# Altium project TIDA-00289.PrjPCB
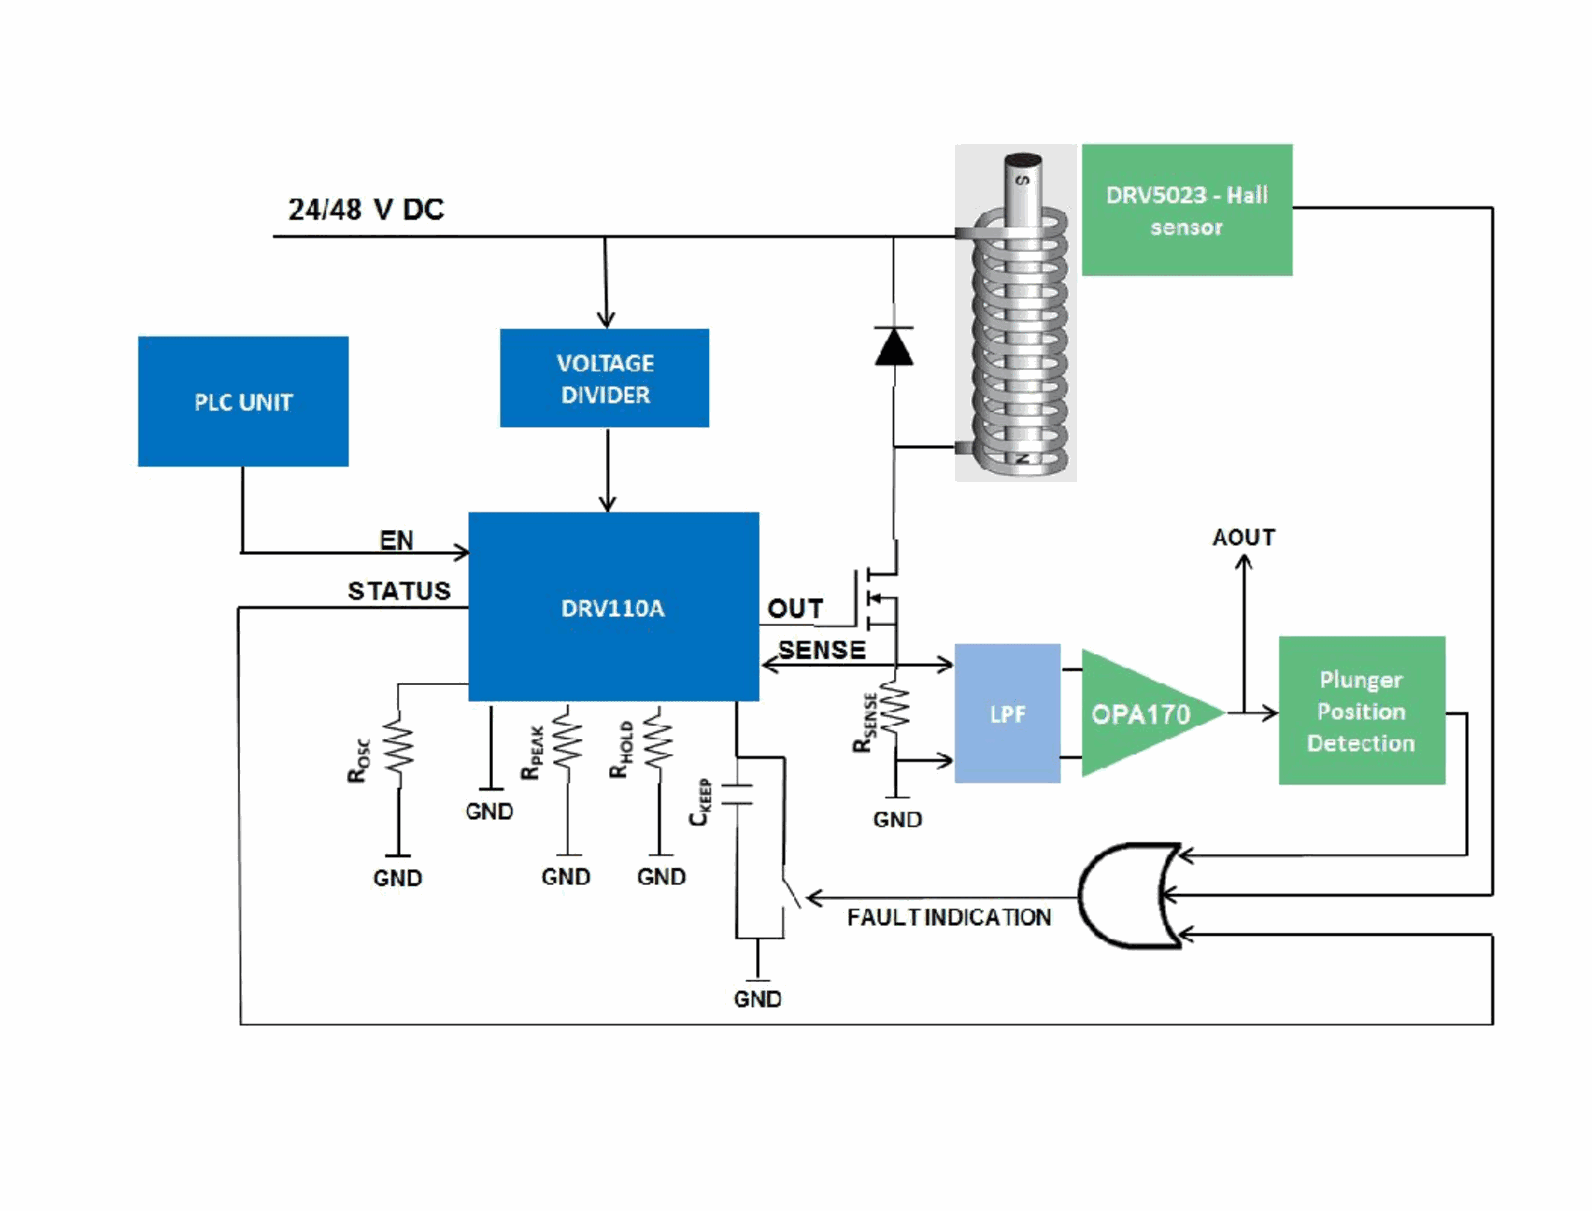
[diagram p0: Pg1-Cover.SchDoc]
CopyrightYear: 2014; PCB_Layout: Sharanu; PCB_Rev: E2; PRJ_Customer: Public Release; PRJ_Engineer: Manu B; PRJ_Number: TIDA-00289; PRJ_Title: Current Controlled Solenoid Driver; SCH_Rev: E2; TechSupport: http://www.ti.com/support
3 sheets, 83 parts. Net scope: global (net labels, ports and power ports of the same name join across sheets).
Board file: TIDA-00289.PcbDoc
Sheets:
  Pg1-Cover.SchDoc
  Pg2-Main.SchDoc
  Pg3_Hardware_ANSI-B.SchDoc

## Sheet Pg1-Cover.SchDoc: Block Diagram
size 431 x 279 mm; Date: Not shown in title block; ApprovedBy: Not shown in title block; CheckedBy: Not shown in title block; Author: Not shown in title block; CompanyName: Not shown in title block; Engineer: Not shown in title block; Organization: Not shown in title block; Address1: Not shown in title block; Address2: Not shown in title block; Address3: Not shown in title block; Address4: Not shown in title block; DocumentNumber: 1; Revision: Use project parameter SCH_Rev; SheetNumber: 1; SheetTotal: 3; PageSetup: Record=PageOptions|CenterHorizontal=True|CenterVertical=True|PrintScale=1.00|XCorrection=1.00|YCorrection=1.00|PrintKind=0|BorderSize=5000000|LeftOffset=0|BottomOffset=0|Orientation=2|PaperLength=1000|PaperWidth=1000|Scale=100|PaperSource=15|PrintQuality=600|MediaType=1|DitherType=10|PaperKind=Letter|PrintScaleMode=1

## Sheet Pg2-Main.SchDoc: Main
size 431 x 279 mm; Date: Not shown in title block; ApprovedBy: Not shown in title block; CheckedBy: Not shown in title block; Author: Not shown in title block; CompanyName: Not shown in title block; DrawnBy: Sanjay Pithadia; Engineer: Not shown in title block; Organization: Not shown in title block; Address1: Not shown in title block; Address2: Not shown in title block; Address3: Not shown in title block; Address4: Not shown in title block; DocumentNumber: 2; Revision: Use project parameter SCH_Rev; SheetNumber: 2; SheetTotal: 3; PageSetup: Record=PageOptions|CenterHorizontal=True|CenterVertical=True|PrintScale=1.00|XCorrection=1.00|YCorrection=1.00|PrintKind=0|BorderSize=5000000|LeftOffset=0|BottomOffset=0|Orientation=2|PaperLength=1000|PaperWidth=1000|Scale=100|PaperSource=15|PrintQuality=600|MediaType=1|DitherType=10|PaperKind=Letter|PrintScaleMode=1
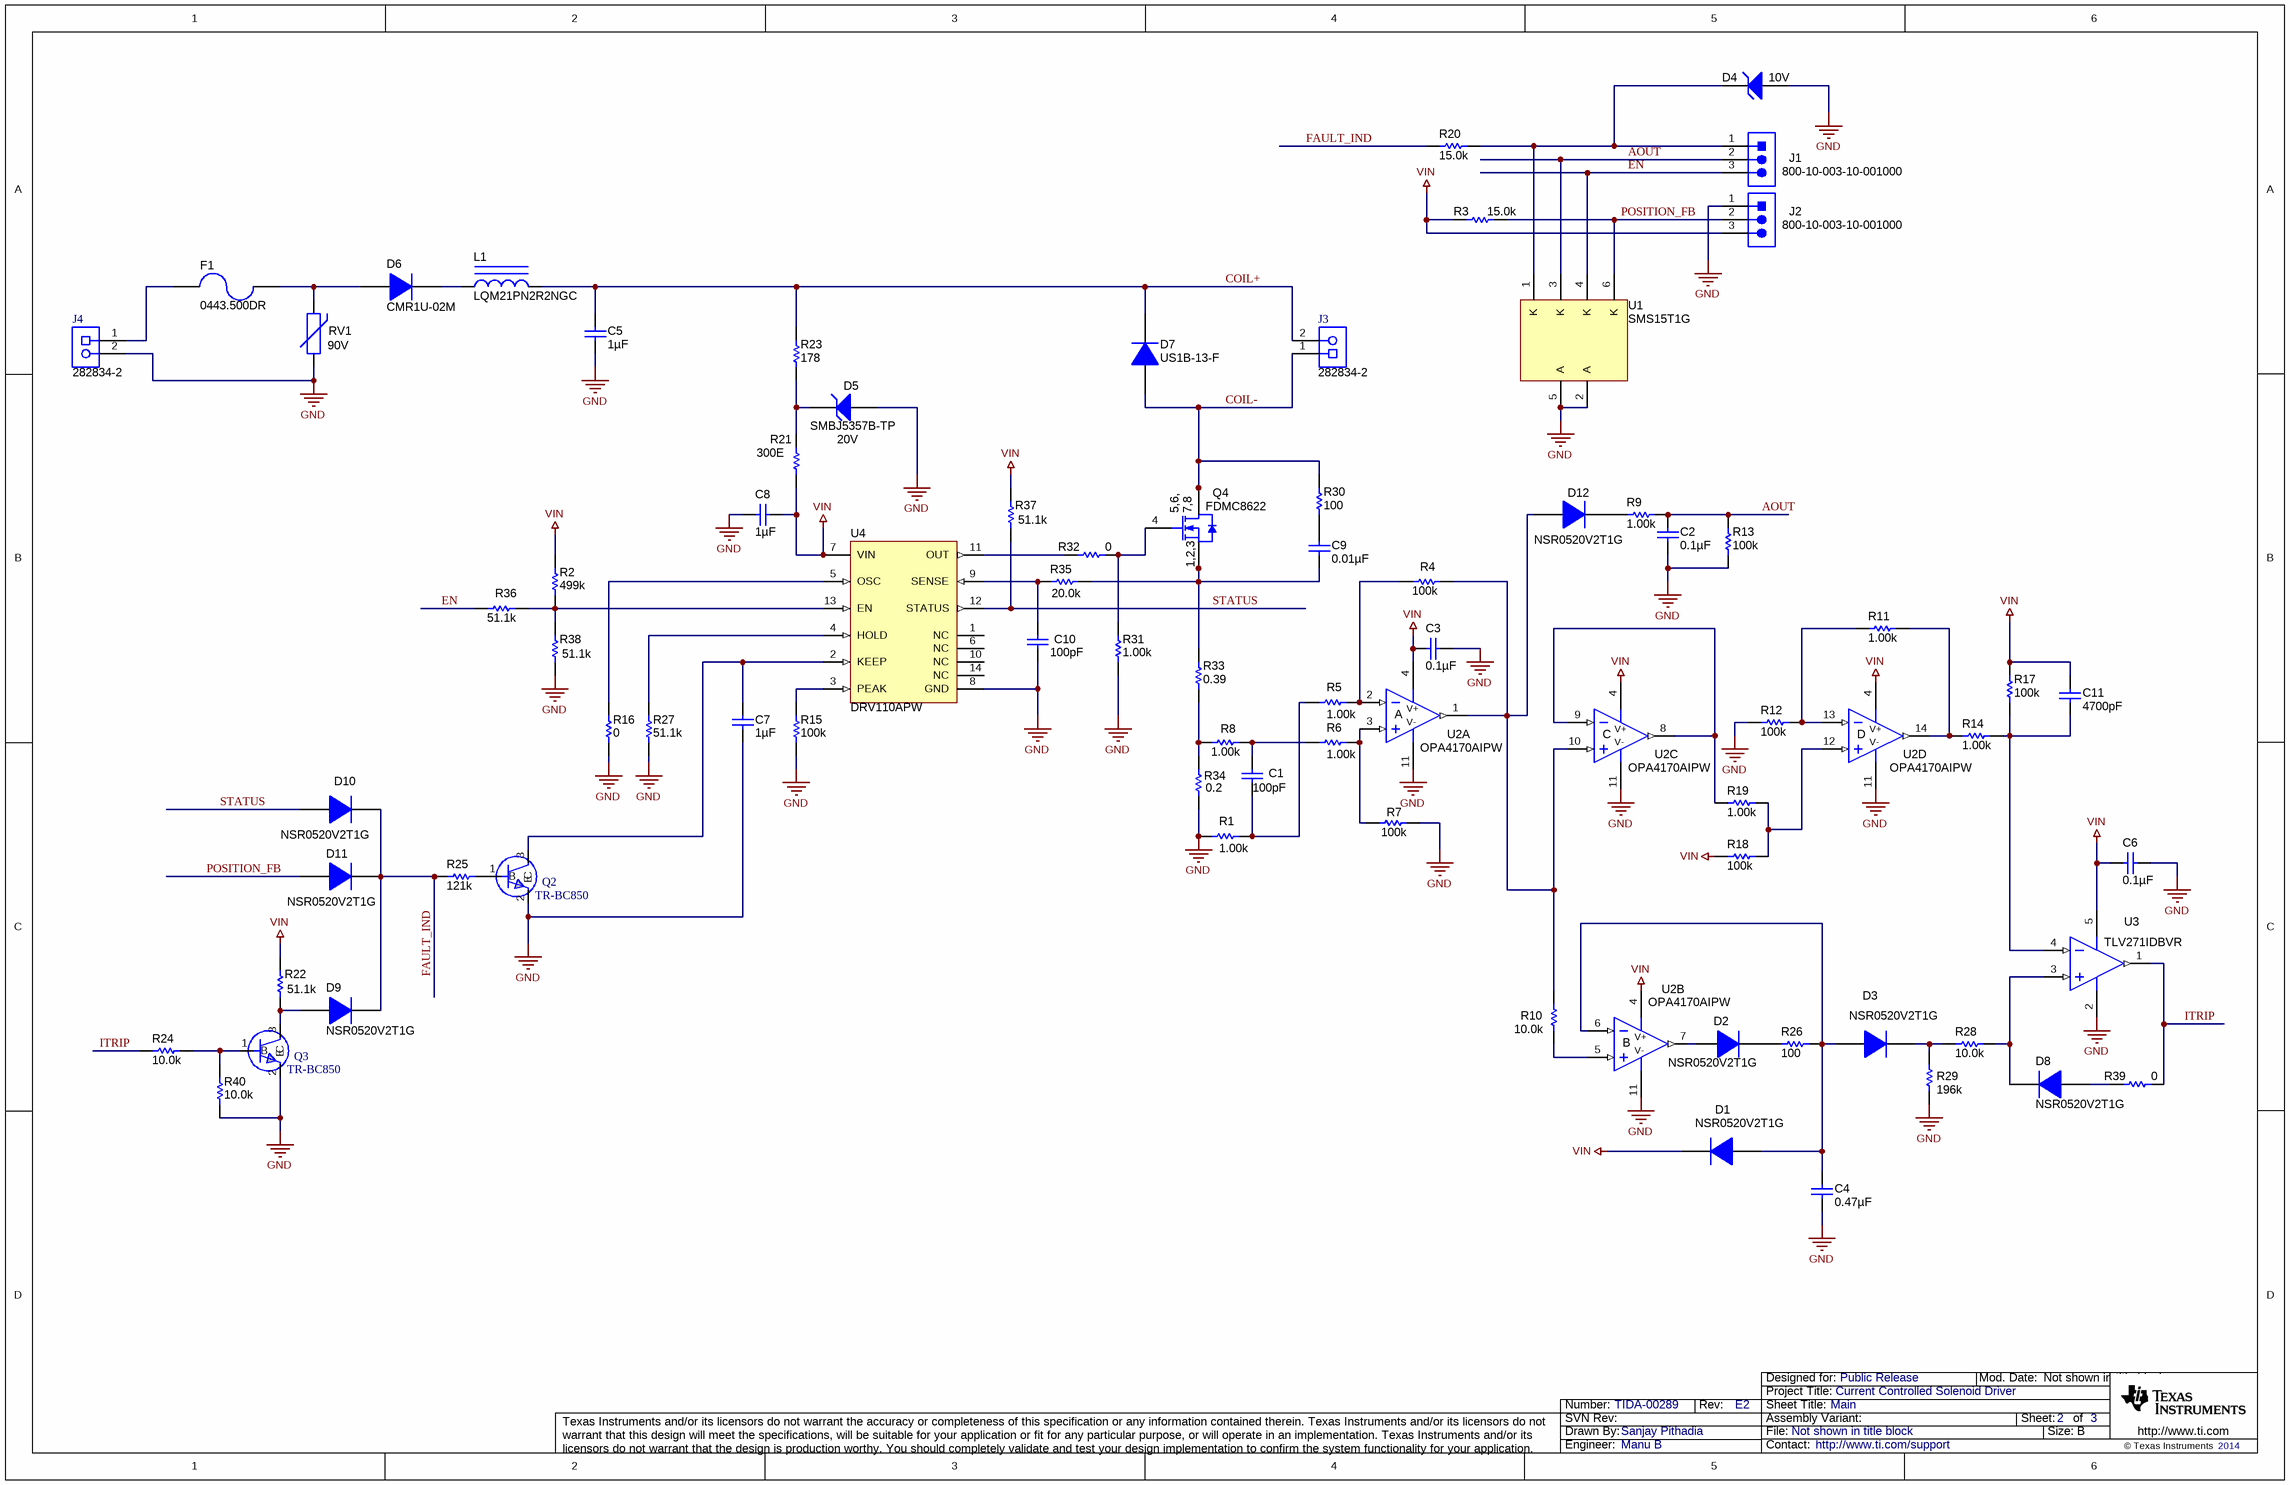
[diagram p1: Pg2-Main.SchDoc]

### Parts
C1  ValueDisplayed: 100pF  [0603]  (hidden comment: 06035A101JAT2A)
C2  ValueDisplayed: 0.1µF  [0603]  (hidden comment: GRM188R71E104KA01D)
C3  ValueDisplayed: 0.1µF  [0603]  (hidden comment: GRM188R71E104KA01D)
C4  ValueDisplayed: 0.47µF  [0603]  (hidden comment: GRM188R71E474KA12D)
C5  ValueDisplayed: 1µF  [1210]  (hidden comment: C3225X7R2A105K200AA)
C6  ValueDisplayed: 0.1µF  [0603]  (hidden comment: GRM188R71E104KA01D)
C7  ValueDisplayed: 1µF  [0603]  (hidden comment: C0603C105K8PACTU)
C8  ValueDisplayed: 1µF  [0603]  (hidden comment: GMK107BJ105KA-T)
C9  ValueDisplayed: 0.01µF  [0805_HV]  (hidden comment: 08051C103KAT2A)
C10  ValueDisplayed: 100pF  [0603]  (hidden comment: 06035A101JAT2A)
C11  ValueDisplayed: 4700pF  [0603]  (hidden comment: GRM188R71E472KA01D)
D1  NSR0520V2T1G  [SOD-523]
D2  NSR0520V2T1G  [SOD-523]
D3  NSR0520V2T1G  [SOD-523]
D4  value 10V  [SOD-123]  (hidden comment: MMSZ5240B-7-F)
D5  SMBJ5357B-TP  value 20V  [SMB]
D6  CMR1U-02M  [SMA]
D7  US1B-13-F  [SMA]
D8  NSR0520V2T1G  [SOD-523]
D9  NSR0520V2T1G  [SOD-523]
D10  NSR0520V2T1G  [SOD-523]
D11  NSR0520V2T1G  [SOD-523]
D12  NSR0520V2T1G  [SOD-523]
F1  0443.500DR  [FUSE_0443]
J1  800-10-003-10-001000  [Connector_GRPB031VWVN-RC]
J2  800-10-003-10-001000  [Connector_GRPB031VWVN-RC]
J3  282834-2  [TEC_282834-2]
J4  282834-2  [TEC_282834-2]
L1  LQM21PN2R2NGC  [0805_HV]
Q2  TR-BC850  [SOT-23]
Q3  TR-BC850  [SOT-23]
Q4  FDMC8622  [PG-TSDSON-8]
R1  value 1.00k  [0603]  (hidden comment: RC0603FR-071KL)
R2  ValueDisplayed: 499k  [0603]  (hidden comment: CRCW0603499KFKEA)
R3  ValueDisplayed: 15.0k  [0603]  (hidden comment: CRCW060315K0FKEA)
R4  ValueDisplayed: 100k  [0603]  (hidden comment: CRCW0603100KFKEA)
R5  value 1.00k  [0603]  (hidden comment: RC0603FR-071KL)
R6  value 1.00k  [0603]  (hidden comment: RC0603FR-071KL)
R7  ValueDisplayed: 100k  [0603]  (hidden comment: CRCW0603100KFKEA)
R8  value 1.00k  [0603]  (hidden comment: RC0603FR-071KL)
R9  value 1.00k  [0603]  (hidden comment: RC0603FR-071KL)
R10  value 10.0k  [0603]  (hidden comment: RT0603BRD0710KL)
R11  value 1.00k  [0603]  (hidden comment: RC0603FR-071KL)
R12  ValueDisplayed: 100k  [0603]  (hidden comment: CRCW0603100KFKEA)
R13  ValueDisplayed: 100k  [0603]  (hidden comment: CRCW0603100KFKEA)
R14  value 1.00k  [0603]  (hidden comment: RC0603FR-071KL)
R15  ValueDisplayed: 100k  [0603]  (hidden comment: CRCW0603100KFKEA)
R16  value 0  [0603]  (hidden comment: CRCW06030000Z0EA)
R17  ValueDisplayed: 100k  [0603]  (hidden comment: CRCW0603100KFKEA)
R18  ValueDisplayed: 100k  [0603]  (hidden comment: CRCW0603100KFKEA)
R19  value 1.00k  [0603]  (hidden comment: RC0603FR-071KL)
R20  ValueDisplayed: 15.0k  [0603]  (hidden comment: CRCW060315K0FKEA)
R21  value 300E  [1210M]  (hidden comment: ERJ-14YJ301U)
R22  ValueDisplayed: 51.1k  [0603]  (hidden comment: CRCW060351K1FKEA)
R23  value 178  [2010]  (hidden comment: CRCW2010178RFKEF)
R24  value 10.0k  [0603]  (hidden comment: RT0603BRD0710KL)
R25  ValueDisplayed: 121k  [0603]  (hidden comment: CRCW0603121KFKEA)
R26  ValueDisplayed: 100  [0603]  (hidden comment: CRCW0603100RFKEA)
R27  ValueDisplayed: 51.1k  [0603]  (hidden comment: CRCW060351K1FKEA)
R28  value 10.0k  [0603]  (hidden comment: RT0603BRD0710KL)
R29  ValueDisplayed: 196k  [0603]  (hidden comment: CRCW0603196KFKEA)
R30  value 100  [0805_HV]  (hidden comment: RT0805BRD07100RL)
R31  value 1.00k  [0603]  (hidden comment: RC0603FR-071KL)
R32  value 0  [0603]  (hidden comment: CRCW06030000Z0EA)
R33  value 0.39  [1210M]  (hidden comment: MCR25JZHFLR390)
R34  value 0.2  [1210M]  (hidden comment: MCR25JZHFLR200)
R35  ValueDisplayed: 20.0k  [0603]  (hidden comment: CRCW060320K0FKEA)
R36  ValueDisplayed: 51.1k  [0603]  (hidden comment: CRCW060351K1FKEA)
R37  ValueDisplayed: 51.1k  [0603]  (hidden comment: CRCW060351K1FKEA)
R38  ValueDisplayed: 51.1k  [0603]  (hidden comment: CRCW060351K1FKEA)
R39  value 0  [0603]  (hidden comment: CRCW06030000Z0EA)
R40  value 10.0k  [0603]  (hidden comment: RT0603BRD0710KL)
RV1  value 90V  [VAR_V100ZA4P]  (hidden comment: V100ZA4P)
U1  SMS15T1G  [DBV0006A_N]
U2  OPA4170AIPW  [PW0014A_N]  (parts A,B,C,D of 4)
U3  TLV271IDBVR  [DBV0005A_N]
U4  DRV110APW  [PW0014A_N]

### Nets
GND: C2.2 C3.1 C4.2 C5.2 C6.1 C7.1 C8.2 C10.2 D4.2(A) D5.2(A) J2.1 J4.2 Q2.2(E) Q3.2(E) R1.2 R7.1 R12.1 R13.1 R15.2 R16.2 R27.1 R29.1 R31.1 R34.1 R38.1 R40.1 RV1.1 U1.2(A) U1.5(A) U2.11(V-) U3.2(GND) U4.8(GND)
VIN: C3.2 C6.2 C8.1 C11.2 D1.1(K) J2.3 R2.1 R3.1 R17.1 R18.1 R21.1 R22.2 R37.2 U2.4(V+) U3.5(VDD) U4.7(VIN)
AOUT: C2.1 J1.2 R9.2 R13.2 U1.3(K)
COIL+: C5.1 D7.1(K) J3.2 L1.2 R23.2
COIL-: D7.2(A) J3.1 Q4.5(D) Q4.6(D) Q4.7(D) Q4.8(D) Q4.9(D) R30.2
EN: J1.3 R36.2 U1.4(K)
FAULT_IND: D9.1(K) D10.1(K) D11.1(K) R20.1 R25.1
ITRIP: R24.2 R39.2 U3.1(OUT)
POSITION_FB: D11.2(A) J2.2 R3.2 U1.6(K)
STATUS: D10.2(A) R37.1 U4.12(STATUS)
NetC1_1: C1.1 R6.2 R8.2
NetC1_2: C1.2 R1.1 R5.2
NetC4_1: C4.1 D1.2(A) D3.2(A) R26.2 U2.6(IN-)
NetC7_2: C7.2 Q2.3(C) U4.2(KEEP)
NetC9_1: C9.1 R30.1
NetC9_2: C9.2 Q4.1(S) Q4.2(S) Q4.3(S) R33.2 R35.2
NetC10_1: C10.1 R35.1 U4.9(SENSE)
NetC11_1: C11.1 R14.2 R17.2 U3.4(IN-)
NetD2_1: D2.1(K) R26.1
NetD2_2: D2.2(A) U2.7(OUT)
NetD3_1: D3.1(K) R28.1 R29.2
NetD4_1: D4.1(K) J1.1 R20.2 U1.1(K)
NetD5_1: D5.1(K) R21.2 R23.1
NetD6_1: D6.1(K) L1.1
NetD6_2: D6.2(A) F1.1 RV1.2
NetD8_1: D8.1(K) R28.2 U3.3(IN+)
NetD8_2: D8.2(A) R39.1
NetD9_2: D9.2(A) Q3.3(C) R22.1
NetD12_1: D12.1(K) R9.1
NetD12_2: D12.2(A) R4.1 R10.2 U2.1(OUT) U2.10(IN+)
NetF1_2: F1.2 J4.1
NetQ2_1: Q2.1(B) R25.2
NetQ3_1: Q3.1(B) R24.1 R40.2
NetQ4_4: Q4.4(G) R31.2 R32.1
NetR2_2: R2.2 R36.1 R38.2 U4.13(EN)
NetR4_2: R4.2 R5.1 U2.2(IN-)
NetR6_1: R6.1 R7.2 U2.3(IN+)
NetR8_1: R8.1 R33.1 R34.2
NetR10_1: R10.1 U2.5(IN+)
NetR11_1: R11.1 R12.2 U2.13(IN-)
NetR11_2: R11.2 R14.1 U2.14(OUT)
NetR15_1: R15.1 U4.3(PEAK)
NetR16_1: R16.1 U4.5(OSC)
NetR18_2: R18.2 R19.2 U2.12(IN+)
NetR19_1: R19.1 U2.8(OUT) U2.9(IN-)
NetR27_2: R27.2 U4.4(HOLD)
NetR32_2: R32.2 U4.11(OUT)

Not connected (* = marked no-connect by the designer): U4 1(NC) 6(NC) 10(NC) 14(NC)

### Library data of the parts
C1 C10 = 06035A101JAT2A: CAP, CERM, 100pF, 50V, +/-5%, C0G/NP0, 0603; Manufacturer: AVX; Polarized: N; CompType: Capacitor; U/M: EA; Cap_F: 0.0000000001; Tolerance_%: 5; ESR_Ohm: 0.119; Value1: 0.119 ohm; VDC_V: 50; TaMin_C: -55; TaMax_C: 125
C2 C3 C6 = GRM188R71E104KA01D: CAP, CERM, 0.1uF, 25V, +/-10%, X7R, 0603; Manufacturer: MuRata; Polarized: N; CompType: Capacitor; U/M: EA; Cap_F: 0.0000001; Tolerance_%: 10; Value1: Unknown; VDC_V: 25; TaMin_C: -55; TaMax_C: 125
C4 = GRM188R71E474KA12D: CAP, CERM, 0.47uF, 25V, +/-10%, X7R, 0603; Manufacturer: MuRata; Polarized: N; CompType: Capacitor; U/M: EA; Cap_F: 0.00000047; Tolerance_%: 10; Value1: Unknown; VDC_V: 25; TaMin_C: -55; TaMax_C: 125
C5 = C3225X7R2A105K200AA: CAP, CERM, 1uF, 100V, +/-10%, X7R, 1210; Manufacturer: TDK; Polarized: N; CompType: Capacitor; U/M: EA; Cap_F: 0.000001; Tolerance_%: 10; Value1: Unknown; VDC_V: 100; TaMin_C: -55; TaMax_C: 125
C7 = C0603C105K8PACTU: CAP, CERM, 1uF, 10V, +/-10%, X5R, 0603; Manufacturer: Kemet; Polarized: N; CompType: Capacitor; U/M: EA; Cap_F: 0.000001; Tolerance_%: 10; Value1: Unknown; TaMin_C: -55; TaMax_C: 85
C8 = GMK107BJ105KA-T: CAP, CERM, 1uF, 35V, +/-10%, X5R, 0603; Manufacturer: Taiyo Yuden; Polarized: N; CompType: Capacitor; U/M: EA; Cap_F: 0.000001; Tolerance_%: 10; Value1: Unknown; VDC_V: 35; TaMin_C: -55; TaMax_C: 85
C9 = 08051C103KAT2A: CAP, CERM, 0.01uF, 100V, +/-10%, X7R, 0805; Manufacturer: AVX; Polarized: N; CompType: Capacitor; U/M: EA; Cap_F: 0.00000001; Tolerance_%: 10; ESR_Ohm: 0.078; Value1: 0.078 ohm; VDC_V: 100; TaMin_C: -55; TaMax_C: 125; Cap_Case: 0805
C11 = GRM188R71E472KA01D: CAP, CERM, 4700pF, 25V, +/-10%, X7R, 0603; Manufacturer: MuRata; Polarized: N; CompType: Capacitor; U/M: EA; Cap_F: 0.0000000047; Tolerance_%: 10; Value1: Unknown; VDC_V: 25; TaMin_C: -55; TaMax_C: 125
D1-D3 D8-D12 = SBR0220T5-7: DIODE SCHOTTKY 20V 0.5A SOD523; Manufacturer: Diodes Inc.; U/M: EA; Vr_V: 20; TJmax_C: 150; Type: Super Barrier Rectifier
D4 = MMSZ5240B-7-F: Diode, Zener, 10V, 500mW, SOD-123; Manufacturer: Diodes Inc.; SymbolCreator: a0412235; U/M: EA; Power_W: 0.5; Vz_V: 10; Value1: 0.5W; RJA_CperW: 350
D5 = SMBJ5357B-TP: Diode, Zener, 20V, 5 W, SMB; Manufacturer: Micro Commercial Components; SymbolCreator: a0412235; U/M: EA; Power_W: 5; Vz_V: 20; Value1: 5W; RJA_CperW: 226
D6 = CMR1U-02M: Diode, Ultrafast, 200V, 1A, SMA; Manufacturer: Central Semiconductor; U/M: EA; Vf_V: 1; Value2: 1V; Vr_V: 200; TJmax_C: 175; RJC_CperW: 30
D7 = US1B-13-F: Diode, Ultrafast, 100V, 1A, SMA; Manufacturer: Diodes Inc.; U/M: EA; Vf_V: 1; Value2: 1V; Vr_V: 100; TJmax_C: 150; RJC_CperW: 30
F1 = 0443.500DR: Fuse, 0.5A, 250V, SMD; Manufacturer: Littelfuse; U/M: EA; OpeningTime_100%_min: 4; OpeningTime_200%_max: 120; VDC_V: 250; Interrupt_AC: 50; Irating_A: 0.5; Rtyp_Ohm: 0.6; MeltingTyp: 1.61; Vdrop: 0.448; Soldering_Wave_MaxTemp_C: 260; Soldering_Wave_MaxTime_s: 3; Soldering_Reflow_MaxTime_s: 20
J1 J2 = 800-10-003-10-001000: Header, 3x1, 100mil, SMT; Manufacturer: Mill-Max; SymbolCreator: a0799628; U/M: EA
J3 J4 = 282834-2: Terminal Block, 2x1, 2.54mm, TH; Manufacturer: TE Connectivity; SymbolCreator: a0412235; U/M: EA
L1 = LQM21PN2R2NGC: Inductor, Shielded, Ferrite, 2.2 uH, 0.8A, 0.23 ohm, SMD; Manufacturer: MuRata; Value: 2.2 uH; Ind_H: 2.2E-6; ValueDisplayed: 2.2 µH; Imax_A: 0.8; Irms: 0.8A @ 0C rise; DCR_ohm: 0.23
Q2 Q3 = TR-BC850: Transistor, N-Chan GP, 45V, 100mA; PartNumber: BC850x; Manufacturer: Philips; Area: 14105; Value: BC850x
Q4 = BSZ440N10NS3 G: MOSFET N-CH 100V 4A POWER33; Manufacturer: Fairchild Semiconductor; Alternate Manufacturer: None; U/M: EA; ChType: N; Rdson45_Ohm: 56 mOHM; QgTyp_nC: 6.8; IdsMax_A: 18
R1 R5 R6 R8 R9 R11 R14 R19 R31 = RC0603FR-071KL: RES, 1.00k ohm, 1%, 0.1W, 0603; Manufacturer: Yageo America; CompType: Resistor; Res_ohm: 1000; Value_Code: 1k00; Tolerance_%: 1; Power_W: 0.1; VDC_V: 150; TempCo: 200 ppm/C; EIA_Code: E96; U/M: EA
R2 = CRCW0603499KFKEA: RES, 499 k, 1%, 0.1 W, 0603; Manufacturer: Vishay-Dale; CompType: Resistor; Res_ohm: 499000; Value: 499k; Tolerance_%: 1; Power_W: 0.1; Value2: 0.1W; VDC_V: 75; TempCo: 100 ppm/C; EIA_Code: E96; U/M: EA
R3 R20 = CRCW060315K0FKEA: RES, 15.0 k, 1%, 0.1 W, 0603; Manufacturer: Vishay-Dale; CompType: Resistor; Res_ohm: 15000; Value: 15.0k; Value_Code: 15k0; Tolerance_%: 1; Power_W: 0.1; Value2: 0.1W; VDC_V: 75; TempCo: 100 ppm/C; EIA_Code: E96; U/M: EA
R4 R7 R12 R13 R15 R17 R18 = CRCW0603100KFKEA: RES, 100 k, 1%, 0.1 W, 0603; Manufacturer: Vishay-Dale; CompType: Resistor; Res_ohm: 100000; Value: 100k; Tolerance_%: 1; Power_W: 0.1; Value2: 0.1W; VDC_V: 75; TempCo: 100 ppm/C; EIA_Code: E96; U/M: EA
R10 R24 R28 R40 = RT0603BRD0710KL: RES, 10.0k ohm, 0.1%, 0.1W, 0603; Manufacturer: Yageo America; CompType: Resistor; Res_ohm: 10000; Value_Code: 10k0; Tolerance_%: 0.1; VDC_V: 75; TempCo: 25 ppm/C; EIA_Code: E192; U/M: EA
R16 R32 R39 = CRCW06030000Z0EA: RES, 0 ohm, 5%, 0.1W, 0603; Manufacturer: Vishay-Dale; CompType: Resistor; Value_Code: 0000; Tolerance_%: 5; Power_W: 0.1; VDC_V: 75; TempCo: 200 ppm/C; EIA_Code: E24; U/M: EA
R21 = MCR25JZHJ000: RES 300 OHM 1/2W 5% 1210 SMD; Manufacturer: Panasonic Electronic Components; CompType: Resistor; Res_ohm: 300; Value_Code: 0000; Tolerance_%: 5; Power_W: 0.5; Value2: 0.5W; VDC_V: 200; TempCo: 20 ppm/C; EIA_Code: E24; U/M: EA
R22 R27 R36-R38 = CRCW060351K1FKEA: RES, 51.1 k, 1%, 0.1 W, 0603; Manufacturer: Vishay-Dale; CompType: Resistor; Res_ohm: 51100; Value: 51.1k; Value_Code: 51k1; Tolerance_%: 1; Power_W: 0.1; Value2: 0.1W; VDC_V: 75; TempCo: 100 ppm/C; EIA_Code: E96; U/M: EA
R23 = CRCW2010178RFKEF: RES, 178 ohm, 1%, 0.75W, 2010; Manufacturer: Vishay-Dale; CompType: Resistor; Value_Code: 178R; Tolerance_%: 1; Power_W: 0.75; VDC_V: 400; TempCo: 100 ppm/C; EIA_Code: E96; U/M: EA
R25 = CRCW0603121KFKEA: RES, 121 k, 1%, 0.1 W, 0603; Manufacturer: Vishay-Dale; CompType: Resistor; Res_ohm: 121000; Value: 121k; Tolerance_%: 1; Power_W: 0.1; Value2: 0.1W; VDC_V: 75; TempCo: 100 ppm/C; EIA_Code: E96; U/M: EA
R26 = CRCW0603100RFKEA: RES, 100, 1%, 0.1 W, 0603; Manufacturer: Vishay-Dale; CompType: Resistor; Value: 100; Value_Code: 100R; Tolerance_%: 1; Power_W: 0.1; Value2: 0.1W; VDC_V: 75; TempCo: 100 ppm/C; EIA_Code: E96; U/M: EA
R29 = CRCW0603196KFKEA: RES, 196 k, 1%, 0.1 W, 0603; Manufacturer: Vishay-Dale; CompType: Resistor; Res_ohm: 196000; Value: 196k; Tolerance_%: 1; Power_W: 0.1; Value2: 0.1W; VDC_V: 75; TempCo: 100 ppm/C; EIA_Code: E96; U/M: EA
R30 = RT0805BRD07100RL: RES, 100 ohm, 0.1%, 0.125W, 0805; Manufacturer: Yageo America; CompType: Resistor; Value_Code: 100R; Tolerance_%: 0.1; Power_W: 0.125; VDC_V: 150; TempCo: 25 ppm/C; EIA_Code: E192; U/M: EA
R33 = MCR25JZHFLR390: RES, 0.39 ohm, 1%, 0.5W, 1210; Manufacturer: Rohm; CompType: Resistor; Value_Code: R390; Tolerance_%: 1; Power_W: 0.5; VDC_V: 0; TempCo: 200 ppm/C; EIA_Code: E96; U/M: EA
R34 = MCR25JZHFLR200: RES, 0.2 ohm, 1%, 0.5W, 1210; Manufacturer: Rohm; CompType: Resistor; Value_Code: R200; Tolerance_%: 1; Power_W: 0.5; VDC_V: 0; TempCo: 200 ppm/C; EIA_Code: E96; U/M: EA
R35 = CRCW060320K0FKEA: RES, 20.0 k, 1%, 0.1 W, 0603; Manufacturer: Vishay-Dale; CompType: Resistor; Res_ohm: 20000; Value: 20.0k; Value_Code: 20k0; Tolerance_%: 1; Power_W: 0.1; Value2: 0.1W; VDC_V: 75; TempCo: 100 ppm/C; EIA_Code: E96; U/M: EA
RV1 = B72207S2301K101: VARISTOR 90V 2.5KA DISC 10MM; SymbolCreator: a0412235
U1 = SMS12T1G: TVS DIODE 15VWM 29VC SC746; Manufacturer: ON Semiconductor; U/M: EA
U2 = OPA4170AIPW: 36V, Single-Supply, SOT553, Low-Power OPERATIONAL AMPLIFIERS Value Line Series, PW0014A; Alternate Manufacturer: None; Manufacturer: Texas Instruments; CompType: IC; U/M: EA
U3 = TLV271IDBVR: 550 uA/Ch, 3 MHz, Rail-to-Rail Output Operational Amplifier, 2.7 to 16 V, -40 to 125 degC, 5-pin SOT23 (DBV0005A), Green (RoHS & no Sb/Br); Manufacturer: Texas Instruments; Alternate Manufacturer: None; Alternate PartNumber: Equivalent; CMRR(Min)(dB): 69; GBW(Typ)(MHz): 3; IIB(Max)(pA): 60; Iq per channel(Max)(mA): 0.66; Number of Channels: 1; Offset Drift(Typ)(uV/C): 2; Packing: LARGE T&R; Rating: Catalog; Slew Rate(Typ)(V/us): 2.4; Sub Family: Low Supply Voltage Amplifier (<=2.7V), Precision Amplifier; Total Supply Voltage(Max)(+5V is 5, +/-5V is 10): 16; Total Supply Voltage(Min)(+5V is 5, +/-5V is 10): 2.7; Vio (25C)(Max)(mV): 5
U4 = DRV110APW: POWER SAVING SOLENOID CONTROLLER WITH INTEGRATED SUPPLY REGULATION, PW0014A; Alternate Manufacturer: None; Manufacturer: Texas Instruments; SymbolCreator: a0411947; CompType: IC; U/M: EA

## Sheet Pg3_Hardware_ANSI-B.SchDoc: Hardware - Miscellaneous
size 431 x 279 mm; Date: Not shown in title block; ApprovedBy: Not shown in title block; CheckedBy: Not shown in title block; Author: Not shown in title block; CompanyName: Not shown in title block; Engineer: Not shown in title block; Organization: Not shown in title block; Address1: Not shown in title block; Address2: Not shown in title block; Address3: Not shown in title block; Address4: Not shown in title block; DocumentNumber: 3; Revision: Use project parameter SCH_Rev; SheetNumber: 3; SheetTotal: 3; PageSetup: Record=PageOptions|CenterHorizontal=True|CenterVertical=True|PrintScale=1.00|XCorrection=1.00|YCorrection=1.00|PrintKind=0|BorderSize=5000000|LeftOffset=0|BottomOffset=0|Orientation=2|PaperLength=1000|PaperWidth=1000|Scale=100|PaperSource=15|PrintQuality=600|MediaType=1|DitherType=10|PaperKind=Letter|PrintScaleMode=1
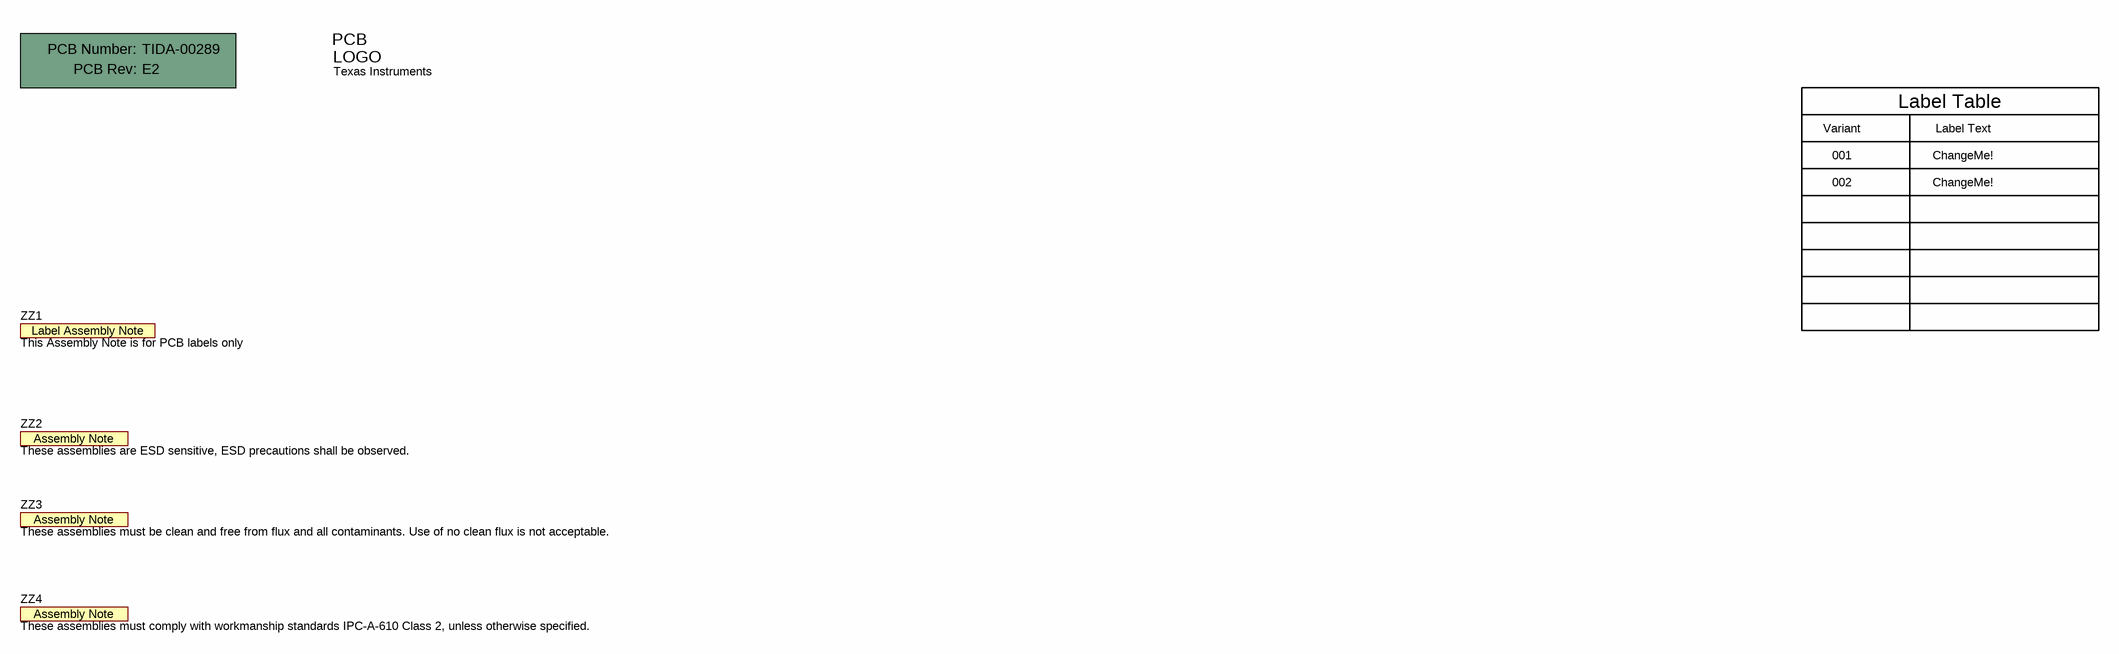
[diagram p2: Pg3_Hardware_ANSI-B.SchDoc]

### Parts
!PCB  Printed Circuit Board  (value not drawn)  (mechanical)
Logo1  Texas Instruments  [TI_Stacked_SolderMask_Small]  (no BOM)
ZZ1  This Assembly Note is for PCB labels only  [AssemblyNoteLabel]  (no BOM)
ZZ2  These assemblies are ESD sensitive, ESD precautions shall be observed.  [AssemblyNote]  (no BOM)
ZZ3  These assemblies must be clean and free from flux and all contaminants. Use of no clean flux is not acceptable.  [AssemblyNote]  (no BOM)
ZZ4  These assemblies must comply with workmanship standards IPC-A-610 Class 2, unless otherwise specified.  [AssemblyNote]  (no BOM)

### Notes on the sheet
- Label Table
- Variant
- 001
- Label Text
- ChangeMe!
- 002

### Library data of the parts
!PCB = PCB: Manufacturer: Any; PartNumber: TIDA-00289; SymbolCreator: a0412235
Logo1 = TI_Logo: Texas Instrument Corporate Signature; SymbolCreator: codlsc
ZZ1 = AssemblyNoteLabel: SymbolCreator: a0412235
ZZ2-ZZ4 = AssemblyNote: SymbolCreator: codlsc

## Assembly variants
001: not fitted C9 R30 R31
